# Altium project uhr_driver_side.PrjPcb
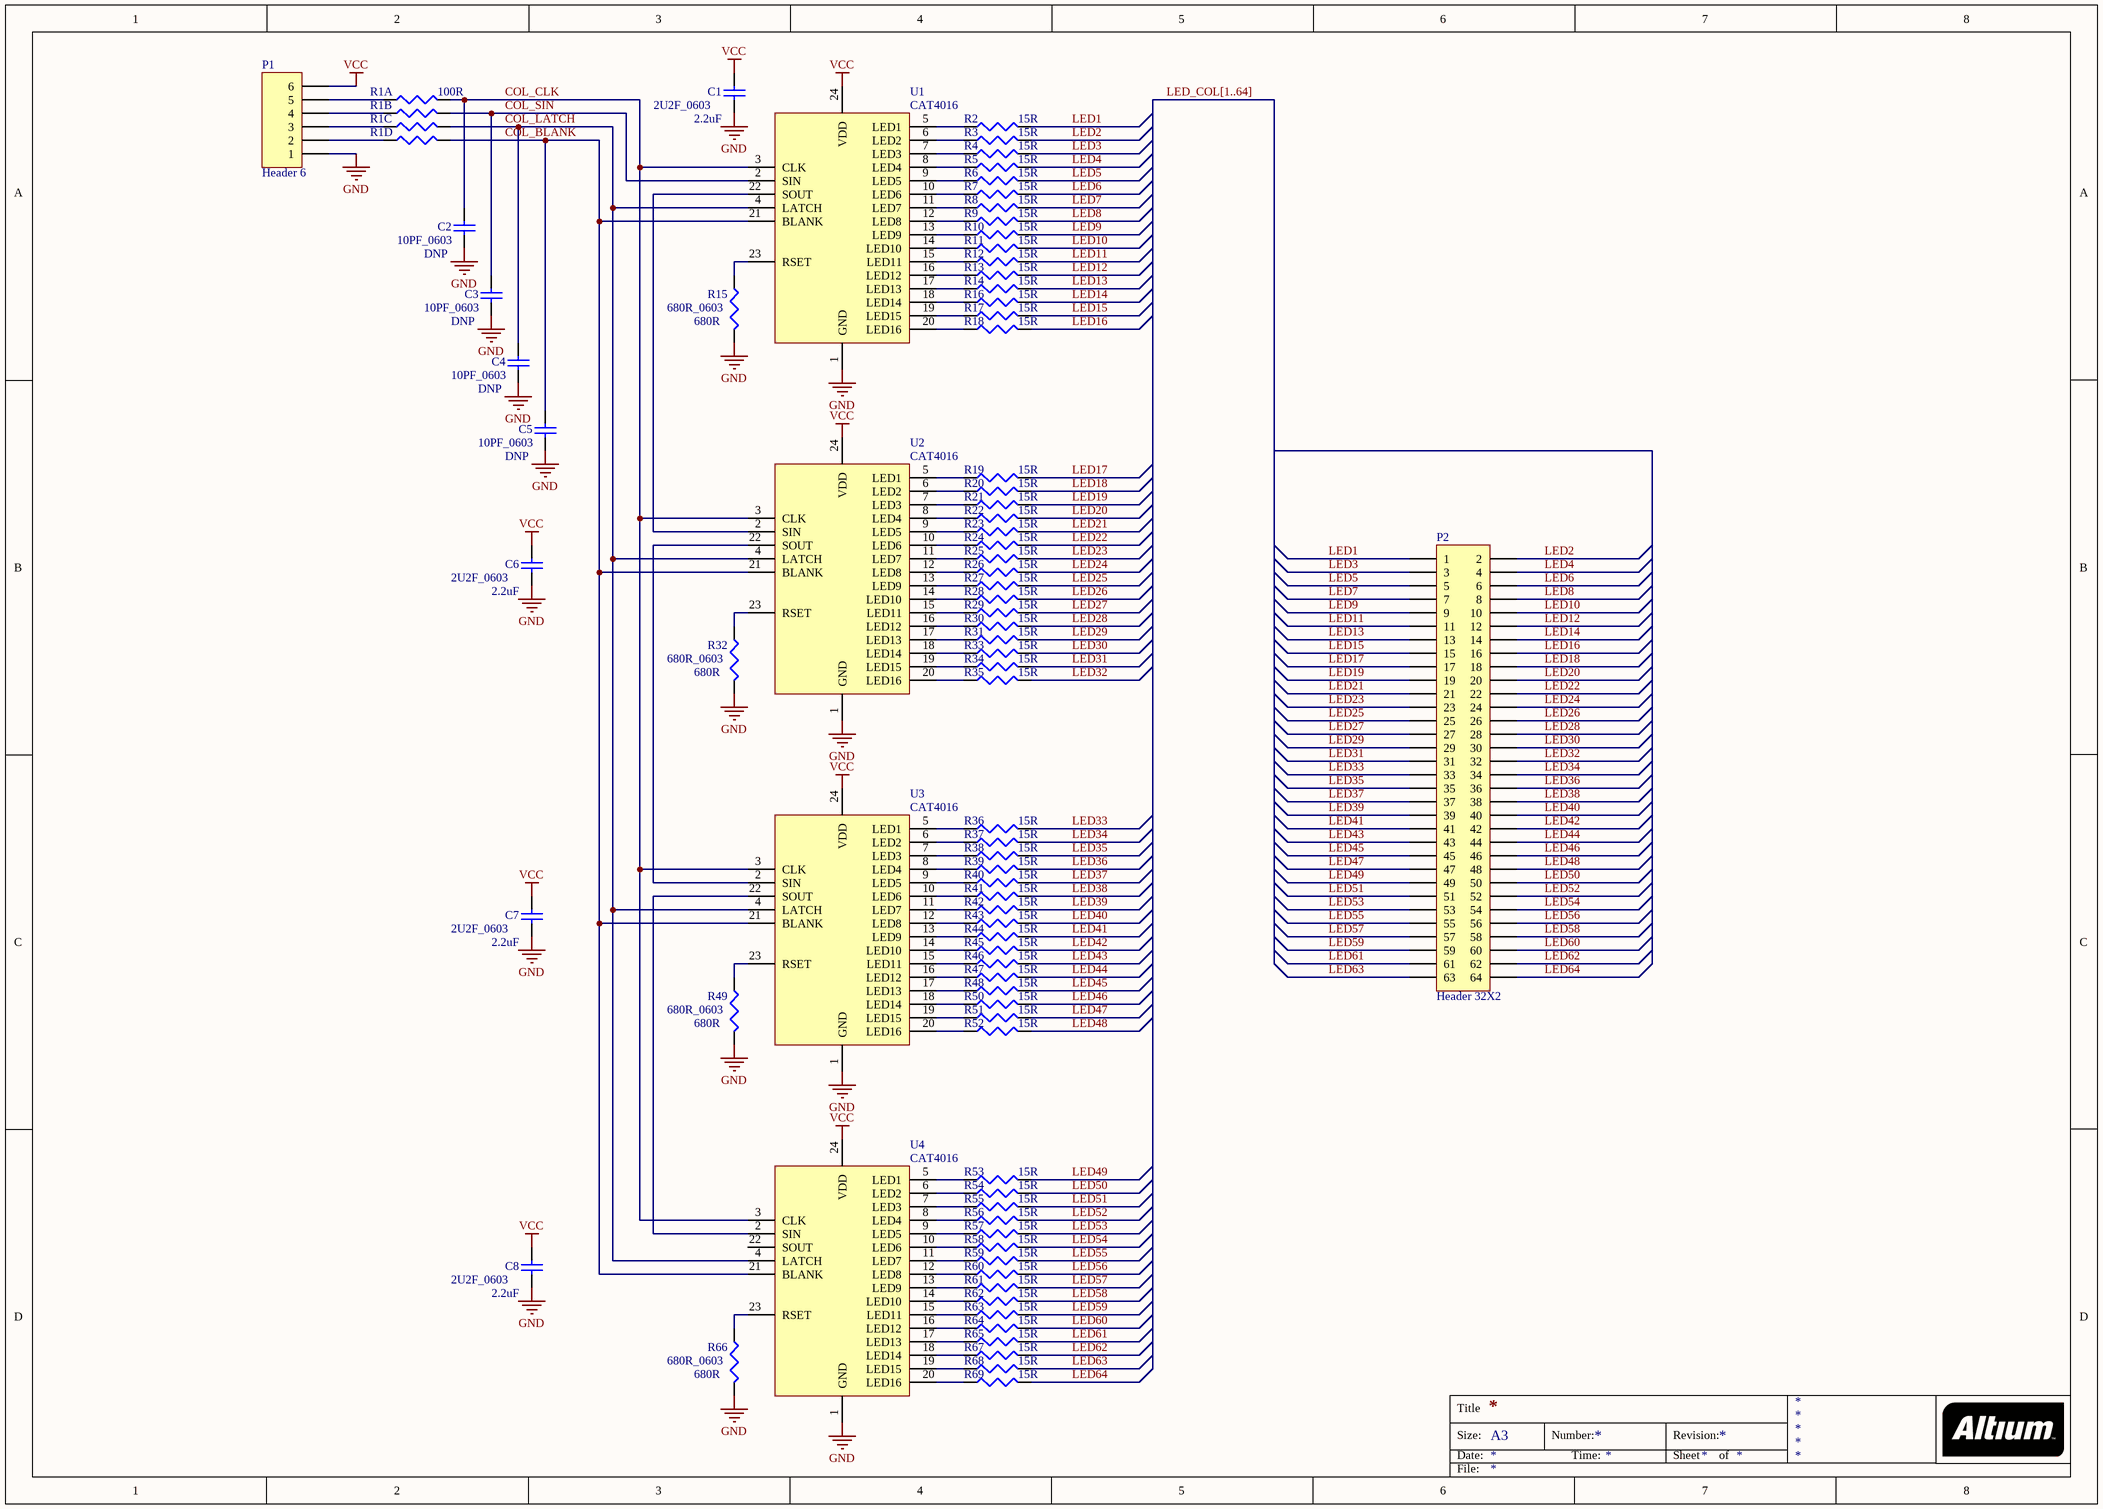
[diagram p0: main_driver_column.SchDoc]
2 sheets, 130 parts. Net scope: global (net labels, ports and power ports of the same name join across sheets).
Board file: uhr_driver_board.PcbDoc
Sheets:
  main_driver_column.SchDoc
  main_driver_row.SchDoc

## Sheet main_driver_column.SchDoc
size A3

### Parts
C1  2U2F_0603  value 2.2uF  [C0603]
C2  10PF_0603  value DNP  [C0603]
C3  10PF_0603  value DNP  [C0603]
C4  10PF_0603  value DNP  [C0603]
C5  10PF_0603  value DNP  [C0603]
C6  2U2F_0603  value 2.2uF  [C0603]
C7  2U2F_0603  value 2.2uF  [C0603]
C8  2U2F_0603  value 2.2uF  [C0603]
P1  Header 6  [HDR1X6_1MM]
P2  Header 32X2  [HDR2X32_1MM]
R1  value 100R  [BCN16]  (hidden comment: Res_Array_BCN16)  (parts A,B,C,D of 4)
R2  value 15R  [R1206]  (hidden comment: 15R_1206)
R3  value 15R  [R1206]  (hidden comment: 15R_1206)
R4  value 15R  [R1206]  (hidden comment: 15R_1206)
R5  value 15R  [R1206]  (hidden comment: 15R_1206)
R6  value 15R  [R1206]  (hidden comment: 15R_1206)
R7  value 15R  [R1206]  (hidden comment: 15R_1206)
R8  value 15R  [R1206]  (hidden comment: 15R_1206)
R9  value 15R  [R1206]  (hidden comment: 15R_1206)
R10  value 15R  [R1206]  (hidden comment: 15R_1206)
R11  value 15R  [R1206]  (hidden comment: 15R_1206)
R12  value 15R  [R1206]  (hidden comment: 15R_1206)
R13  value 15R  [R1206]  (hidden comment: 15R_1206)
R14  value 15R  [R1206]  (hidden comment: 15R_1206)
R15  680R_0603  value 680R  [R0603]
R16  value 15R  [R1206]  (hidden comment: 15R_1206)
R17  value 15R  [R1206]  (hidden comment: 15R_1206)
R18  value 15R  [R1206]  (hidden comment: 15R_1206)
R19  value 15R  [R1206]  (hidden comment: 15R_1206)
R20  value 15R  [R1206]  (hidden comment: 15R_1206)
R21  value 15R  [R1206]  (hidden comment: 15R_1206)
R22  value 15R  [R1206]  (hidden comment: 15R_1206)
R23  value 15R  [R1206]  (hidden comment: 15R_1206)
R24  value 15R  [R1206]  (hidden comment: 15R_1206)
R25  value 15R  [R1206]  (hidden comment: 15R_1206)
R26  value 15R  [R1206]  (hidden comment: 15R_1206)
R27  value 15R  [R1206]  (hidden comment: 15R_1206)
R28  value 15R  [R1206]  (hidden comment: 15R_1206)
R29  value 15R  [R1206]  (hidden comment: 15R_1206)
R30  value 15R  [R1206]  (hidden comment: 15R_1206)
R31  value 15R  [R1206]  (hidden comment: 15R_1206)
R32  680R_0603  value 680R  [R0603]
R33  value 15R  [R1206]  (hidden comment: 15R_1206)
R34  value 15R  [R1206]  (hidden comment: 15R_1206)
R35  value 15R  [R1206]  (hidden comment: 15R_1206)
R36  value 15R  [R1206]  (hidden comment: 15R_1206)
R37  value 15R  [R1206]  (hidden comment: 15R_1206)
R38  value 15R  [R1206]  (hidden comment: 15R_1206)
R39  value 15R  [R1206]  (hidden comment: 15R_1206)
R40  value 15R  [R1206]  (hidden comment: 15R_1206)
R41  value 15R  [R1206]  (hidden comment: 15R_1206)
R42  value 15R  [R1206]  (hidden comment: 15R_1206)
R43  value 15R  [R1206]  (hidden comment: 15R_1206)
R44  value 15R  [R1206]  (hidden comment: 15R_1206)
R45  value 15R  [R1206]  (hidden comment: 15R_1206)
R46  value 15R  [R1206]  (hidden comment: 15R_1206)
R47  value 15R  [R1206]  (hidden comment: 15R_1206)
R48  value 15R  [R1206]  (hidden comment: 15R_1206)
R49  680R_0603  value 680R  [R0603]
R50  value 15R  [R1206]  (hidden comment: 15R_1206)
R51  value 15R  [R1206]  (hidden comment: 15R_1206)
R52  value 15R  [R1206]  (hidden comment: 15R_1206)
R53  value 15R  [R1206]  (hidden comment: 15R_1206)
R54  value 15R  [R1206]  (hidden comment: 15R_1206)
R55  value 15R  [R1206]  (hidden comment: 15R_1206)
R56  value 15R  [R1206]  (hidden comment: 15R_1206)
R57  value 15R  [R1206]  (hidden comment: 15R_1206)
R58  value 15R  [R1206]  (hidden comment: 15R_1206)
R59  value 15R  [R1206]  (hidden comment: 15R_1206)
R60  value 15R  [R1206]  (hidden comment: 15R_1206)
R61  value 15R  [R1206]  (hidden comment: 15R_1206)
R62  value 15R  [R1206]  (hidden comment: 15R_1206)
R63  value 15R  [R1206]  (hidden comment: 15R_1206)
R64  value 15R  [R1206]  (hidden comment: 15R_1206)
R65  value 15R  [R1206]  (hidden comment: 15R_1206)
R66  680R_0603  value 680R  [R0603]
R67  value 15R  [R1206]  (hidden comment: 15R_1206)
R68  value 15R  [R1206]  (hidden comment: 15R_1206)
R69  value 15R  [R1206]  (hidden comment: 15R_1206)
U1  CAT4016  [SOIC-24_W]
U2  CAT4016  [SOIC-24_W]
U3  CAT4016  [SOIC-24_W]
U4  CAT4016  [SOIC-24_W]

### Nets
GND: C1.1 C2.1 C3.1 C4.1 C5.1 C6.1 C7.1 C8.1 P1.1 R15.2 R32.2 R49.2 R66.2 U1.1(GND) U2.1(GND) U3.1(GND) U4.1(GND)
VCC: C1.2 C6.2 C7.2 C8.2 P1.6 U1.24(VDD) U2.24(VDD) U3.24(VDD) U4.24(VDD)
COL_BLANK: C5.2 R1.5 U1.21(BLANK) U2.21(BLANK) U3.21(BLANK) U4.21(BLANK)
COL_CLK: C2.2 R1.8 U1.3(CLK) U2.3(CLK) U3.3(CLK) U4.3(CLK)
COL_LATCH: C4.2 R1.6 U1.4(LATCH) U2.4(LATCH) U3.4(LATCH) U4.4(LATCH)
COL_SIN: C3.2 R1.7 U1.2(SIN)
LED1: P2.1 R2.2
LED2: P2.2 R3.2
LED3: P2.3 R4.2
LED4: P2.4 R5.2
LED5: P2.5 R6.2
LED6: P2.6 R7.2
LED7: P2.7 R8.2
LED8: P2.8 R9.2
LED9: P2.9 R10.2
LED10: P2.10 R11.2
LED11: P2.11 R12.2
LED12: P2.12 R13.2
LED13: P2.13 R14.2
LED14: P2.14 R16.2
LED15: P2.15 R17.2
LED16: P2.16 R18.2
LED17: P2.17 R19.2
LED18: P2.18 R20.2
LED19: P2.19 R21.2
LED20: P2.20 R22.2
LED21: P2.21 R23.2
LED22: P2.22 R24.2
LED23: P2.23 R25.2
LED24: P2.24 R26.2
LED25: P2.25 R27.2
LED26: P2.26 R28.2
LED27: P2.27 R29.2
LED28: P2.28 R30.2
LED29: P2.29 R31.2
LED30: P2.30 R33.2
LED31: P2.31 R34.2
LED32: P2.32 R35.2
LED33: P2.33 R36.2
LED34: P2.34 R37.2
LED35: P2.35 R38.2
LED36: P2.36 R39.2
LED37: P2.37 R40.2
LED38: P2.38 R41.2
LED39: P2.39 R42.2
LED40: P2.40 R43.2
LED41: P2.41 R44.2
LED42: P2.42 R45.2
LED43: P2.43 R46.2
LED44: P2.44 R47.2
LED45: P2.45 R48.2
LED46: P2.46 R50.2
LED47: P2.47 R51.2
LED48: P2.48 R52.2
LED49: P2.49 R53.2
LED50: P2.50 R54.2
LED51: P2.51 R55.2
LED52: P2.52 R56.2
LED53: P2.53 R57.2
LED54: P2.54 R58.2
LED55: P2.55 R59.2
LED56: P2.56 R60.2
LED57: P2.57 R61.2
LED58: P2.58 R62.2
LED59: P2.59 R63.2
LED60: P2.60 R64.2
LED61: P2.61 R65.2
LED62: P2.62 R67.2
LED63: P2.63 R68.2
LED64: P2.64 R69.2
NetP1_2: P1.2 R1.4
NetP1_3: P1.3 R1.3
NetP1_4: P1.4 R1.2
NetP1_5: P1.5 R1.1
NetR2_1: R2.1 U1.5(LED1)
NetR3_1: R3.1 U1.6(LED2)
NetR4_1: R4.1 U1.7(LED3)
NetR5_1: R5.1 U1.8(LED4)
NetR6_1: R6.1 U1.9(LED5)
NetR7_1: R7.1 U1.10(LED6)
NetR8_1: R8.1 U1.11(LED7)
NetR9_1: R9.1 U1.12(LED8)
NetR10_1: R10.1 U1.13(LED9)
NetR11_1: R11.1 U1.14(LED10)
NetR12_1: R12.1 U1.15(LED11)
NetR13_1: R13.1 U1.16(LED12)
NetR14_1: R14.1 U1.17(LED13)
NetR15_1: R15.1 U1.23(RSET)
NetR16_1: R16.1 U1.18(LED14)
NetR17_1: R17.1 U1.19(LED15)
NetR18_1: R18.1 U1.20(LED16)
NetR19_1: R19.1 U2.5(LED1)
NetR20_1: R20.1 U2.6(LED2)
NetR21_1: R21.1 U2.7(LED3)
NetR22_1: R22.1 U2.8(LED4)
NetR23_1: R23.1 U2.9(LED5)
NetR24_1: R24.1 U2.10(LED6)
NetR25_1: R25.1 U2.11(LED7)
NetR26_1: R26.1 U2.12(LED8)
NetR27_1: R27.1 U2.13(LED9)
NetR28_1: R28.1 U2.14(LED10)
NetR29_1: R29.1 U2.15(LED11)
NetR30_1: R30.1 U2.16(LED12)
NetR31_1: R31.1 U2.17(LED13)
NetR32_1: R32.1 U2.23(RSET)
NetR33_1: R33.1 U2.18(LED14)
NetR34_1: R34.1 U2.19(LED15)
NetR35_1: R35.1 U2.20(LED16)
NetR36_1: R36.1 U3.5(LED1)
NetR37_1: R37.1 U3.6(LED2)
NetR38_1: R38.1 U3.7(LED3)
NetR39_1: R39.1 U3.8(LED4)
NetR40_1: R40.1 U3.9(LED5)
NetR41_1: R41.1 U3.10(LED6)
NetR42_1: R42.1 U3.11(LED7)
NetR43_1: R43.1 U3.12(LED8)
NetR44_1: R44.1 U3.13(LED9)
NetR45_1: R45.1 U3.14(LED10)
NetR46_1: R46.1 U3.15(LED11)
NetR47_1: R47.1 U3.16(LED12)
NetR48_1: R48.1 U3.17(LED13)
NetR49_1: R49.1 U3.23(RSET)
NetR50_1: R50.1 U3.18(LED14)
NetR51_1: R51.1 U3.19(LED15)
NetR52_1: R52.1 U3.20(LED16)
NetR53_1: R53.1 U4.5(LED1)
NetR54_1: R54.1 U4.6(LED2)
NetR55_1: R55.1 U4.7(LED3)
NetR56_1: R56.1 U4.8(LED4)
NetR57_1: R57.1 U4.9(LED5)
NetR58_1: R58.1 U4.10(LED6)
NetR59_1: R59.1 U4.11(LED7)
NetR60_1: R60.1 U4.12(LED8)
NetR61_1: R61.1 U4.13(LED9)
NetR62_1: R62.1 U4.14(LED10)
NetR63_1: R63.1 U4.15(LED11)
NetR64_1: R64.1 U4.16(LED12)
NetR65_1: R65.1 U4.17(LED13)
NetR66_1: R66.1 U4.23(RSET)
NetR67_1: R67.1 U4.18(LED14)
NetR68_1: R68.1 U4.19(LED15)
NetR69_1: R69.1 U4.20(LED16)
NetU1_22: U1.22(SOUT) U2.2(SIN)
NetU2_22: U2.22(SOUT) U3.2(SIN)
NetU3_22: U3.22(SOUT) U4.2(SIN)

Not connected (* = marked no-connect by the designer): U4 22(SOUT)

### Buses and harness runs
bus LED_COL[1..64]

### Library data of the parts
C1-C8 = Cap Semi: Capacitor (Semiconductor SIM Model)
P1 = Header 6: Header, 6-Pin
P2 = Header 32X2: Header, 32-Pin, Dual row
R1 = Res_Array_BCN16: Resistor
R2-R69 = Res3: Resistor
U1-U4 = CAT4016: 16channel LED driver - constant current

## Sheet main_driver_row.SchDoc
size A3
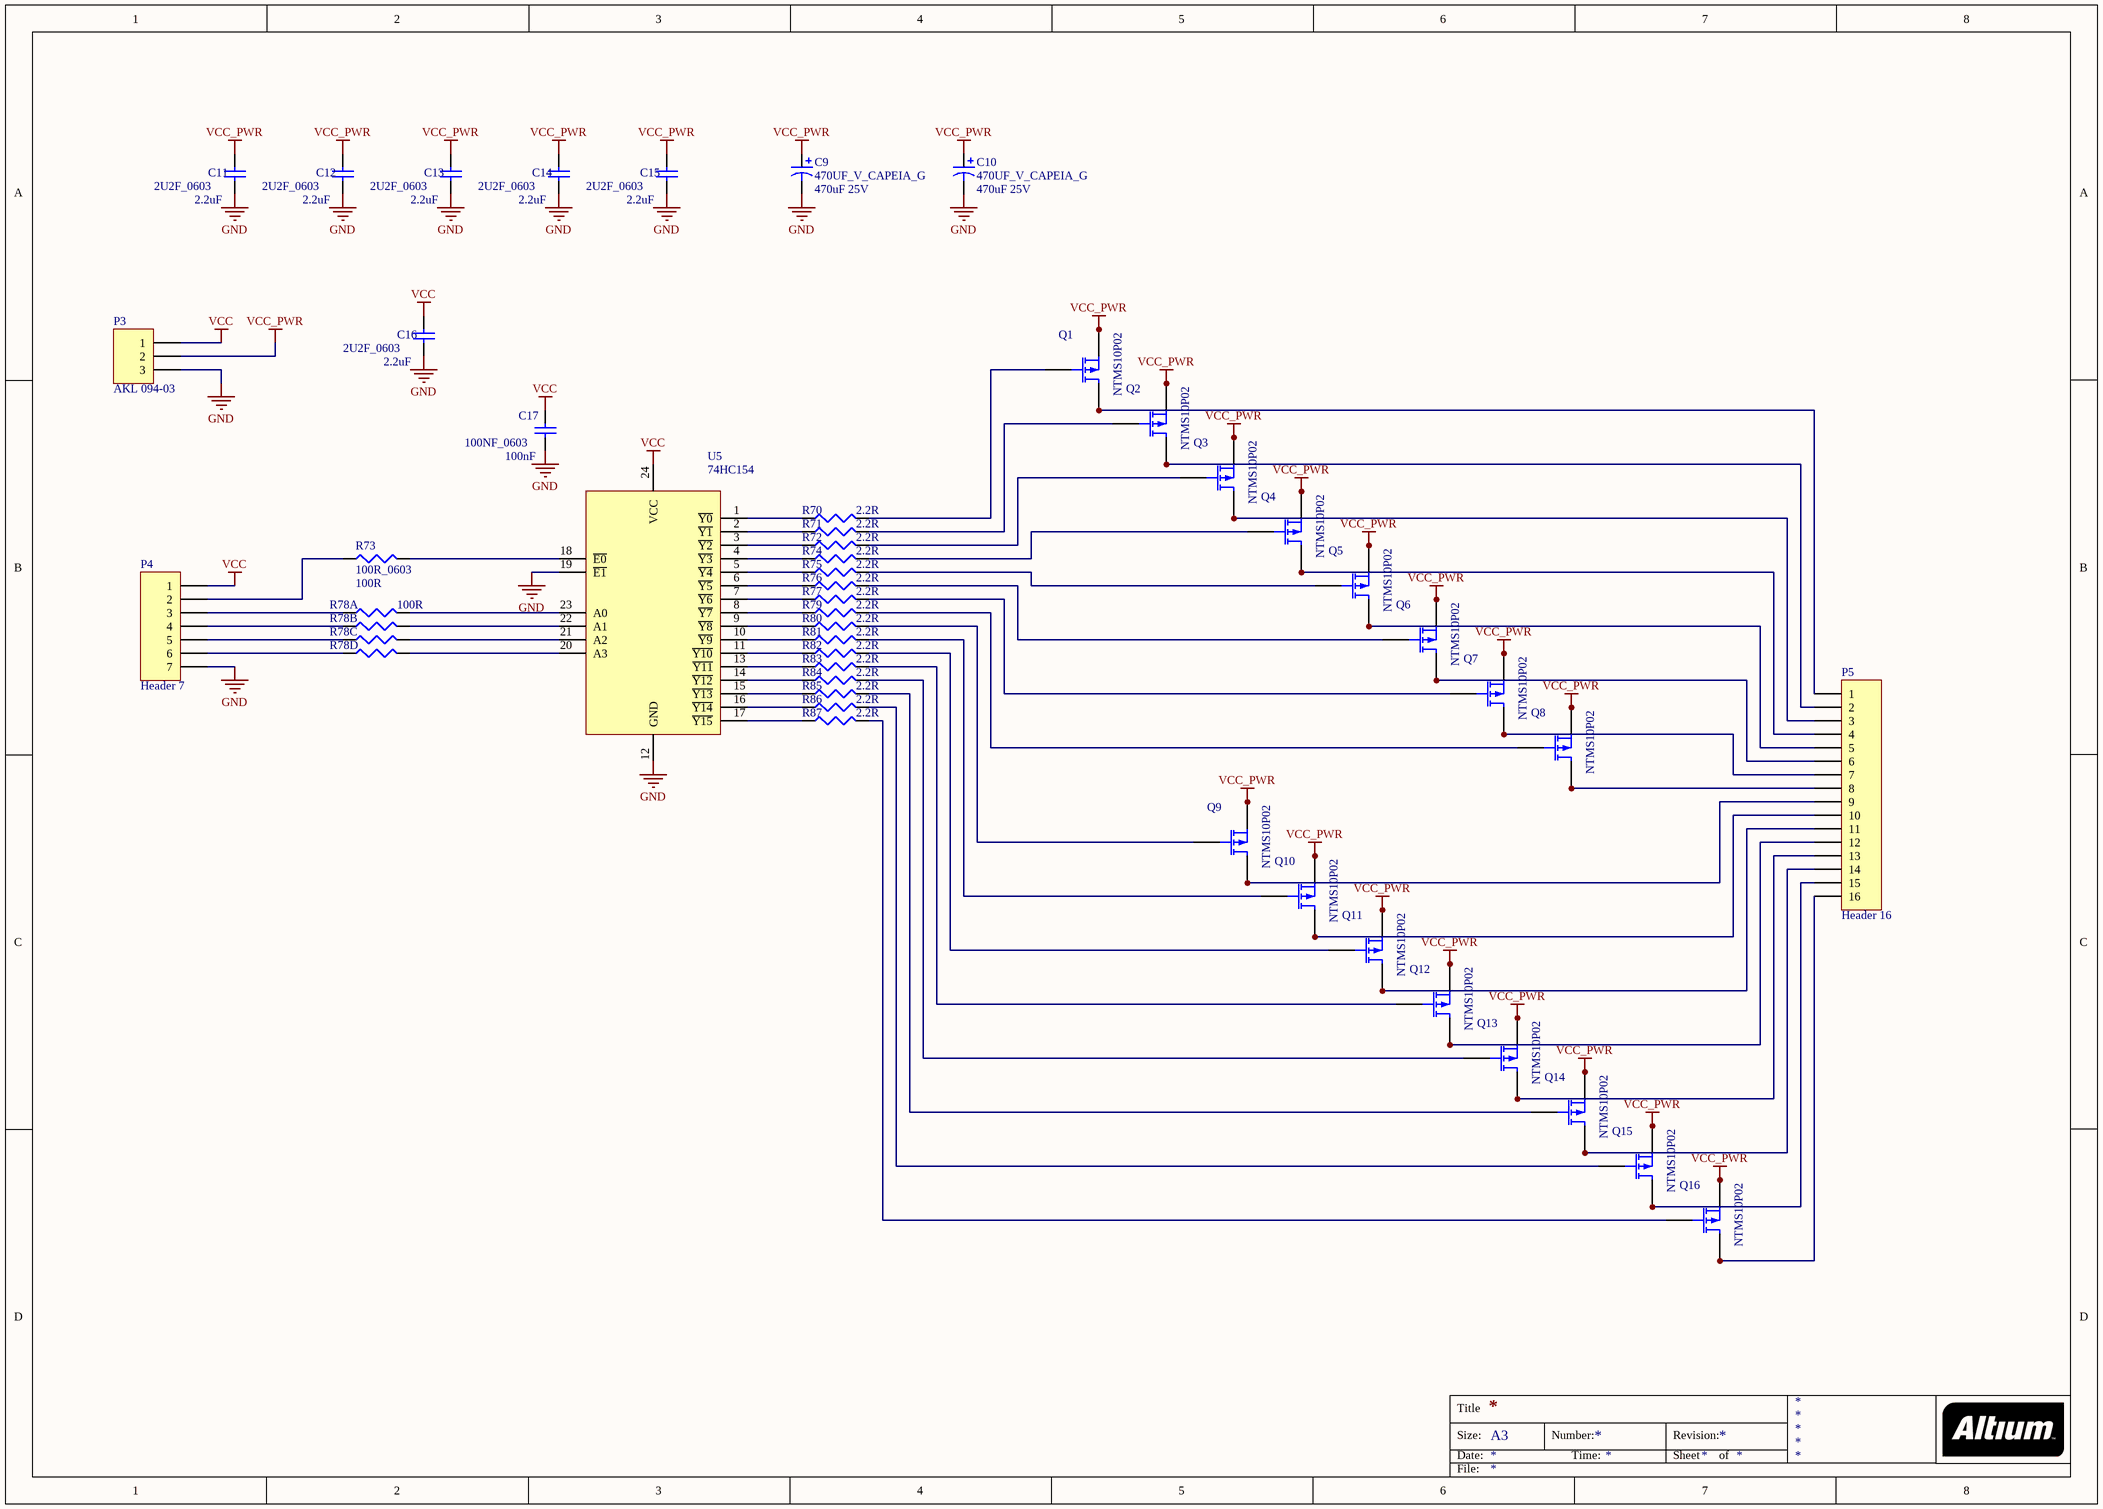
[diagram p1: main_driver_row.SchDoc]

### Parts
C9  470UF_V_CAPEIA_G  value 470uF 25V  [CAPAE_G]
C10  470UF_V_CAPEIA_G  value 470uF 25V  [CAPAE_G]
C11  2U2F_0603  value 2.2uF  [C0603]
C12  2U2F_0603  value 2.2uF  [C0603]
C13  2U2F_0603  value 2.2uF  [C0603]
C14  2U2F_0603  value 2.2uF  [C0603]
C15  2U2F_0603  value 2.2uF  [C0603]
C16  2U2F_0603  value 2.2uF  [C0603]
C17  100NF_0603  value 100nF  [C0603]
P3  AKL 094-03  [Header_3_Screw_5mm]
P4  Header 7  [HDR1X7_1MM]
P5  Header 16  [HDR1X16_1MM]
Q1  NTMS10P02  [SOIC-8]
Q2  NTMS10P02  [SOIC-8]
Q3  NTMS10P02  [SOIC-8]
Q4  NTMS10P02  [SOIC-8]
Q5  NTMS10P02  [SOIC-8]
Q6  NTMS10P02  [SOIC-8]
Q7  NTMS10P02  [SOIC-8]
Q8  NTMS10P02  [SOIC-8]
Q9  NTMS10P02  [SOIC-8]
Q10  NTMS10P02  [SOIC-8]
Q11  NTMS10P02  [SOIC-8]
Q12  NTMS10P02  [SOIC-8]
Q13  NTMS10P02  [SOIC-8]
Q14  NTMS10P02  [SOIC-8]
Q15  NTMS10P02  [SOIC-8]
Q16  NTMS10P02  [SOIC-8]
R70  value 2.2R  [R0805]  (hidden comment: 2R2_0805)
R71  value 2.2R  [R0805]  (hidden comment: 2R2_0805)
R72  value 2.2R  [R0805]  (hidden comment: 2R2_0805)
R73  100R_0603  value 100R  [R0603]
R74  value 2.2R  [R0805]  (hidden comment: 2R2_0805)
R75  value 2.2R  [R0805]  (hidden comment: 2R2_0805)
R76  value 2.2R  [R0805]  (hidden comment: 2R2_0805)
R77  value 2.2R  [R0805]  (hidden comment: 2R2_0805)
R78  value 100R  [BCN16]  (hidden comment: Res_Array_BCN16)  (parts A,B,C,D of 4)
R79  value 2.2R  [R0805]  (hidden comment: 2R2_0805)
R80  value 2.2R  [R0805]  (hidden comment: 2R2_0805)
R81  value 2.2R  [R0805]  (hidden comment: 2R2_0805)
R82  value 2.2R  [R0805]  (hidden comment: 2R2_0805)
R83  value 2.2R  [R0805]  (hidden comment: 2R2_0805)
R84  value 2.2R  [R0805]  (hidden comment: 2R2_0805)
R85  value 2.2R  [R0805]  (hidden comment: 2R2_0805)
R86  value 2.2R  [R0805]  (hidden comment: 2R2_0805)
R87  value 2.2R  [R0805]  (hidden comment: 2R2_0805)
U5  74HC154  [SOIC-24_W]

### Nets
GND: C9.2 C10.2 C11.1 C12.1 C13.1 C14.1 C15.1 C16.1 C17.1 P3.3 P4.7 U5.12(GND) U5.19(~{E1})
VCC: C16.2 C17.2 P3.1 P4.1 U5.24(VCC)
VCC_PWR: C9.1 C10.1 C11.2 C12.2 C13.2 C14.2 C15.2 P3.2 Q1.1(S) Q1.2(S) Q1.3(S) Q2.1(S) Q2.2(S) Q2.3(S) Q3.1(S) Q3.2(S) Q3.3(S) Q4.1(S) Q4.2(S) Q4.3(S) Q5.1(S) Q5.2(S) Q5.3(S) Q6.1(S) Q6.2(S) Q6.3(S) Q7.1(S) Q7.2(S) Q7.3(S) Q8.1(S) Q8.2(S) Q8.3(S) Q9.1(S) Q9.2(S) Q9.3(S) Q10.1(S) Q10.2(S) Q10.3(S) Q11.1(S) Q11.2(S) Q11.3(S) Q12.1(S) Q12.2(S) Q12.3(S) Q13.1(S) Q13.2(S) Q13.3(S) Q14.1(S) Q14.2(S) Q14.3(S) Q15.1(S) Q15.2(S) Q15.3(S) Q16.1(S) Q16.2(S) Q16.3(S)
NetP4_2: P4.2 R73.1
NetP4_3: P4.3 R78.1
NetP4_4: P4.4 R78.2
NetP4_5: P4.5 R78.3
NetP4_6: P4.6 R78.4
NetP5_1: P5.1 Q1.5(D) Q1.6(D) Q1.7(D) Q1.8(D)
NetP5_2: P5.2 Q2.5(D) Q2.6(D) Q2.7(D) Q2.8(D)
NetP5_3: P5.3 Q3.5(D) Q3.6(D) Q3.7(D) Q3.8(D)
NetP5_4: P5.4 Q4.5(D) Q4.6(D) Q4.7(D) Q4.8(D)
NetP5_5: P5.5 Q5.5(D) Q5.6(D) Q5.7(D) Q5.8(D)
NetP5_6: P5.6 Q6.5(D) Q6.6(D) Q6.7(D) Q6.8(D)
NetP5_7: P5.7 Q7.5(D) Q7.6(D) Q7.7(D) Q7.8(D)
NetP5_8: P5.8 Q8.5(D) Q8.6(D) Q8.7(D) Q8.8(D)
NetP5_9: P5.9 Q9.5(D) Q9.6(D) Q9.7(D) Q9.8(D)
NetP5_10: P5.10 Q10.5(D) Q10.6(D) Q10.7(D) Q10.8(D)
NetP5_11: P5.11 Q11.5(D) Q11.6(D) Q11.7(D) Q11.8(D)
NetP5_12: P5.12 Q12.5(D) Q12.6(D) Q12.7(D) Q12.8(D)
NetP5_13: P5.13 Q13.5(D) Q13.6(D) Q13.7(D) Q13.8(D)
NetP5_14: P5.14 Q14.5(D) Q14.6(D) Q14.7(D) Q14.8(D)
NetP5_15: P5.15 Q15.5(D) Q15.6(D) Q15.7(D) Q15.8(D)
NetP5_16: P5.16 Q16.5(D) Q16.6(D) Q16.7(D) Q16.8(D)
NetQ1_4: Q1.4(G) R70.2
NetQ2_4: Q2.4(G) R71.2
NetQ3_4: Q3.4(G) R72.2
NetQ4_4: Q4.4(G) R74.2
NetQ5_4: Q5.4(G) R75.2
NetQ6_4: Q6.4(G) R76.2
NetQ7_4: Q7.4(G) R77.2
NetQ8_4: Q8.4(G) R79.2
NetQ9_4: Q9.4(G) R80.2
NetQ10_4: Q10.4(G) R81.2
NetQ11_4: Q11.4(G) R82.2
NetQ12_4: Q12.4(G) R83.2
NetQ13_4: Q13.4(G) R84.2
NetQ14_4: Q14.4(G) R85.2
NetQ15_4: Q15.4(G) R86.2
NetQ16_4: Q16.4(G) R87.2
NetR70_1: R70.1 U5.1(~{Y0})
NetR71_1: R71.1 U5.2(~{Y1})
NetR72_1: R72.1 U5.3(~{Y2})
NetR73_2: R73.2 U5.18(~{E0})
NetR74_1: R74.1 U5.4(~{Y3})
NetR75_1: R75.1 U5.5(~{Y4})
NetR76_1: R76.1 U5.6(~{Y5})
NetR77_1: R77.1 U5.7(~{Y6})
NetR78_5: R78.5 U5.20(A3)
NetR78_6: R78.6 U5.21(A2)
NetR78_7: R78.7 U5.22(A1)
NetR78_8: R78.8 U5.23(A0)
NetR79_1: R79.1 U5.8(~{Y7})
NetR80_1: R80.1 U5.9(~{Y8})
NetR81_1: R81.1 U5.10(~{Y9})
NetR82_1: R82.1 U5.11(~{Y10})
NetR83_1: R83.1 U5.13(~{Y11})
NetR84_1: R84.1 U5.14(~{Y12})
NetR85_1: R85.1 U5.15(~{Y13})
NetR86_1: R86.1 U5.16(~{Y14})
NetR87_1: R87.1 U5.17(~{Y15})

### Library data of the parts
C9 C10 = Cap Pol1: Polarized Capacitor (Radial)
C11-C17 = Cap Semi: Capacitor (Semiconductor SIM Model)
P3 = Header 3: Header, 3-Pin
P4 = Header 7: Header, 7-Pin
P5 = Header 16: Header, 16-Pin
Q1-Q16 = NTMS10P02: P-Channel MOSFET SO8
R70-R77 R79-R87 = Res3: Resistor
R78 = Res_Array_BCN16: Resistor

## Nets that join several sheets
GND: main_driver_column (17 pins), main_driver_row (13 pins)
VCC: main_driver_column (9 pins), main_driver_row (5 pins)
